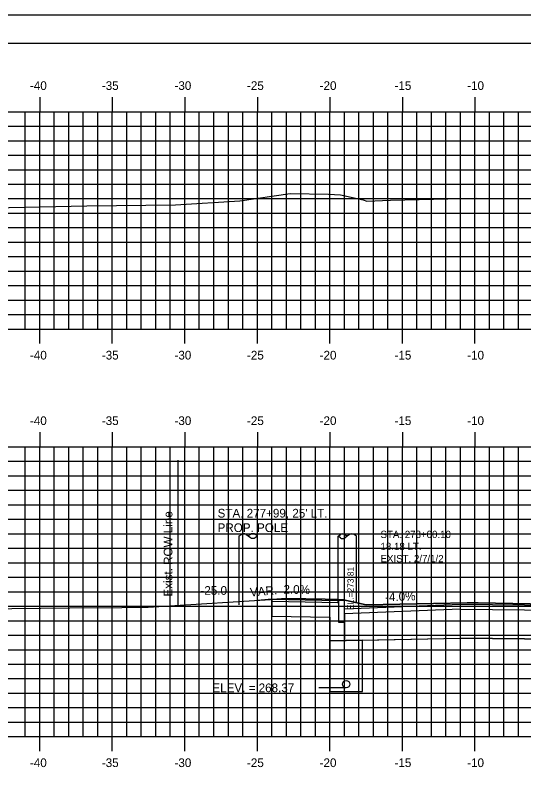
# Model space of a CAD drawing. Extents: x 854453 to 854623, y 366268 to 366378.
# Drawn here: x 854494.8 to 854529.8, y 366325.6 to 366378.2 of the extents above; entities that cross this region are included whole.
import ezdxf

# ---------------------------------------------------------------- set-up
doc = ezdxf.new("R2010")
doc.units = 0
for name, color, linetype in [('ANNOTATION', 7, 'Continuous'), ('BORDER', 7, 'Continuous'), ('D_Curb_Type_1_Lt', 7, 'Continuous'), ('D_Roadway_Edge_Shoulder', 7, 'Continuous'), ('D_Roadway_FinishedGrade', 7, 'Continuous'), ('D_Roadway_Sidewalks_Paved', 7, 'Continuous'), ('D_Roadway_SubGrade', 7, 'Continuous'), ('D_Text_Monospaced', 7, 'Continuous'), ('D_Text_Standard', 7, 'Continuous'), ('D_Utilities_Pole_Joint', 7, 'Continuous'), ('D_Utilities_Text', 7, 'Continuous'), ('E_ROW_Line', 7, 'Continuous'), ('H_V ANNOTATION', 7, 'Continuous'), ('JUNK COM EXC', 7, 'Continuous'), ('junk strct exc', 7, 'Continuous'), ('MAJOR', 7, 'Continuous'), ('MINOR', 7, 'Continuous'), ('PDRAIN', 7, 'Continuous'), ('PLOT BOUNDARY', 7, 'Continuous'), ('S_Roadway_Centerline', 7, 'Continuous'), ('S_Utilities_Pole_Power', 7, 'Continuous')]:
    doc.layers.add(name, color=color, linetype=linetype)

msp = doc.modelspace()

# ---------------------------------------------------------------- linework, layer by layer
at = {"layer": 'BORDER'}
msp.add_line((854621.439, 366376.236), (854461.439, 366376.236), dxfattribs=at)
at = {"layer": 'D_Curb_Type_1_Lt'}
msp.add_lwpolyline([(854517.022, 366337.795), (854517.022, 366336.295), (854517.439, 366336.295), (854517.439, 366337.795)], close=True, dxfattribs=at)
at = {"layer": 'D_Roadway_Edge_Shoulder'}
msp.add_lwpolyline([(854517.439, 366337.212), (854525.439, 366337.532), (854536.439, 366337.422), (854547.439, 366337.202), (854555.437, 366336.882)], dxfattribs=at)
at = {"layer": 'D_Roadway_FinishedGrade'}
msp.add_line((854512.434, 366337.887), (854511.439, 366337.804), dxfattribs=at)
at = {"layer": 'D_Roadway_Sidewalks_Paved'}
msp.add_lwpolyline([(854512.434, 366337.887), (854517.022, 366337.795), (854517.022, 366337.629), (854512.434, 366337.721)], close=True, dxfattribs=at)
at = {"layer": 'D_Roadway_SubGrade'}
msp.add_lwpolyline([(854512.434, 366337.721), (854512.434, 366336.72), (854516.439, 366336.64), (854516.439, 366335.019), (854517.439, 366335.039)], dxfattribs=at)
for points in [[(854525.439, 366337.199), (854517.439, 366336.879), (854517.439, 366335.039), (854525.439, 366335.199)], [(854525.439, 366335.199), (854525.439, 366337.199), (854536.439, 366337.089), (854547.439, 366336.869), (854547.439, 366334.869), (854536.439, 366335.089)]]:
    msp.add_lwpolyline(points, close=True, dxfattribs=at)
at = {"layer": 'D_Text_Standard'}
msp.add_lwpolyline([(854517.564, 366331.768), (854516.366, 366331.768), (854515.686, 366331.768)], dxfattribs=at)
at = {"layer": 'D_Utilities_Pole_Joint'}
for p, q in [((854510.189, 366342.245), (854510.345, 366342.355)), ((854510.657, 366342.355), (854510.813, 366342.245)), ((854510.969, 366342.355), (854510.813, 366342.245)), ((854511.439, 366342.245), (854511.282, 366342.355)), ((854510.189, 366337.487), (854510.189, 366342.245)), ((854510.813, 366342.245), (854510.969, 366342.134)), ((854511.282, 366342.134), (854511.439, 366342.245)), ((854511.439, 366337.487), (854511.439, 366342.245))]:
    msp.add_line(p, q, dxfattribs=at)
for centre, start, end in [((854510.501, 366342.134), 90, 125.2644), ((854510.501, 366342.134), 54.7356, 90), ((854511.126, 366342.134), 90, 125.2644), ((854511.126, 366342.134), 54.7356, 90), ((854511.126, 366342.355), 234.7356, 270), ((854511.126, 366342.355), 270, 305.2644)]:
    msp.add_arc(centre, 0.271, start, end, dxfattribs=at)
at = {"layer": 'E_ROW_Line'}
msp.add_line((854505.984, 366337.468), (854505.984, 366347.468), dxfattribs=at)
at = {"layer": 'JUNK COM EXC'}
for points in [[(854512.435, 366337.865), (854512.434, 366337.865), (854512.434, 366336.72), (854516.439, 366336.64), (854516.439, 366335.019), (854525.439, 366335.199), (854536.439, 366335.089)], [(854537.42, 366337.418), (854526.661, 366337.64), (854525.893, 366337.635), (854518.949, 366337.49), (854517.372, 366337.843), (854516.983, 366337.854), (854516.109, 366337.876), (854513.45, 366337.928), (854512.435, 366337.865)]]:
    msp.add_lwpolyline(points, dxfattribs=at)
at = {"layer": 'junk strct exc'}
msp.add_lwpolyline([(854516.439, 366335.019), (854516.439, 366331.518), (854518.689, 366331.518), (854518.689, 366335.064)], close=True, dxfattribs=at)
at = {"layer": 'MAJOR'}
for p, q in [((854496.439, 366372.523), (854496.439, 366371.521)), ((854501.439, 366372.523), (854501.439, 366371.521)), ((854506.439, 366372.523), (854506.439, 366371.521)), ((854511.439, 366372.523), (854511.439, 366371.521)), ((854516.439, 366372.523), (854516.439, 366371.521)), ((854521.439, 366372.523), (854521.439, 366371.521)), ((854526.439, 366372.523), (854526.439, 366371.521)), ((854466.439, 366371.521), (854606.439, 366371.521)), ((854496.439, 366356.521), (854496.439, 366371.521)), ((854501.439, 366356.521), (854501.439, 366371.521)), ((854506.439, 366356.521), (854506.439, 366371.521)), ((854511.439, 366356.521), (854511.439, 366371.521)), ((854516.439, 366356.521), (854516.439, 366371.521)), ((854521.439, 366356.521), (854521.439, 366371.521)), ((854526.439, 366356.521), (854526.439, 366371.521)), ((854466.439, 366366.521), (854606.439, 366366.521)), ((854466.439, 366361.521), (854606.439, 366361.521)), ((854466.439, 366356.521), (854606.439, 366356.521)), ((854466.439, 366356.521), (854606.439, 366356.521)), ((854496.439, 366355.519), (854496.439, 366356.521)), ((854501.439, 366355.519), (854501.439, 366356.521)), ((854506.439, 366355.519), (854506.439, 366356.521)), ((854511.439, 366355.519), (854511.439, 366356.521)), ((854516.439, 366355.519), (854516.439, 366356.521)), ((854521.439, 366355.519), (854521.439, 366356.521)), ((854526.439, 366355.519), (854526.439, 366356.521)), ((854496.439, 366349.403), (854496.439, 366348.401)), ((854501.439, 366349.403), (854501.439, 366348.401)), ((854506.439, 366349.403), (854506.439, 366348.401)), ((854511.439, 366349.403), (854511.439, 366348.401)), ((854516.439, 366349.403), (854516.439, 366348.401)), ((854521.439, 366349.403), (854521.439, 366348.401)), ((854526.439, 366349.403), (854526.439, 366348.401)), ((854466.439, 366348.401), (854606.439, 366348.401)), ((854466.439, 366348.401), (854606.439, 366348.401)), ((854496.439, 366328.401), (854496.439, 366348.401)), ((854501.439, 366328.401), (854501.439, 366348.401)), ((854506.439, 366328.401), (854506.439, 366348.401)), ((854511.439, 366328.401), (854511.439, 366348.401)), ((854516.439, 366328.401), (854516.439, 366348.401)), ((854521.439, 366328.401), (854521.439, 366348.401)), ((854526.439, 366328.401), (854526.439, 366348.401)), ((854466.439, 366343.401), (854606.439, 366343.401)), ((854466.439, 366338.401), (854606.439, 366338.401)), ((854466.439, 366333.401), (854606.439, 366333.401)), ((854466.439, 366328.401), (854606.439, 366328.401)), ((854466.439, 366328.401), (854606.439, 366328.401)), ((854496.439, 366327.399), (854496.439, 366328.401)), ((854501.439, 366327.399), (854501.439, 366328.401)), ((854506.439, 366327.399), (854506.439, 366328.401)), ((854511.439, 366327.399), (854511.439, 366328.401)), ((854516.439, 366327.399), (854516.439, 366328.401)), ((854521.439, 366327.399), (854521.439, 366328.401)), ((854526.439, 366327.399), (854526.439, 366328.401))]:
    msp.add_line(p, q, dxfattribs=at)
at = {"layer": 'MINOR'}
for p, q in [((854495.439, 366356.521), (854495.439, 366371.521)), ((854497.439, 366356.521), (854497.439, 366371.521)), ((854498.439, 366356.521), (854498.439, 366371.521)), ((854499.439, 366356.521), (854499.439, 366371.521)), ((854500.439, 366356.521), (854500.439, 366371.521)), ((854502.439, 366356.521), (854502.439, 366371.521)), ((854503.439, 366356.521), (854503.439, 366371.521)), ((854504.439, 366356.521), (854504.439, 366371.521)), ((854505.439, 366356.521), (854505.439, 366371.521)), ((854507.439, 366356.521), (854507.439, 366371.521)), ((854508.439, 366356.521), (854508.439, 366371.521)), ((854509.439, 366356.521), (854509.439, 366371.521)), ((854510.439, 366356.521), (854510.439, 366371.521)), ((854512.439, 366356.521), (854512.439, 366371.521)), ((854513.439, 366356.521), (854513.439, 366371.521)), ((854514.439, 366356.521), (854514.439, 366371.521)), ((854515.439, 366356.521), (854515.439, 366371.521)), ((854517.439, 366356.521), (854517.439, 366371.521)), ((854518.439, 366356.521), (854518.439, 366371.521)), ((854519.439, 366356.521), (854519.439, 366371.521)), ((854520.439, 366356.521), (854520.439, 366371.521)), ((854522.439, 366356.521), (854522.439, 366371.521)), ((854523.439, 366356.521), (854523.439, 366371.521)), ((854524.439, 366356.521), (854524.439, 366371.521)), ((854525.439, 366356.521), (854525.439, 366371.521)), ((854527.439, 366356.521), (854527.439, 366371.521)), ((854528.439, 366356.521), (854528.439, 366371.521)), ((854529.439, 366356.521), (854529.439, 366371.521)), ((854466.439, 366370.521), (854606.439, 366370.521)), ((854466.439, 366369.521), (854606.439, 366369.521)), ((854466.439, 366368.521), (854606.439, 366368.521)), ((854466.439, 366367.521), (854606.439, 366367.521)), ((854466.439, 366365.521), (854606.439, 366365.521)), ((854466.439, 366364.521), (854606.439, 366364.521)), ((854466.439, 366363.521), (854606.439, 366363.521)), ((854466.439, 366362.521), (854606.439, 366362.521)), ((854466.439, 366360.521), (854606.439, 366360.521)), ((854466.439, 366359.521), (854606.439, 366359.521)), ((854466.439, 366358.521), (854606.439, 366358.521)), ((854466.439, 366357.521), (854606.439, 366357.521)), ((854495.439, 366328.401), (854495.439, 366348.401)), ((854497.439, 366328.401), (854497.439, 366348.401)), ((854498.439, 366328.401), (854498.439, 366348.401)), ((854499.439, 366328.401), (854499.439, 366348.401)), ((854500.439, 366328.401), (854500.439, 366348.401)), ((854502.439, 366328.401), (854502.439, 366348.401)), ((854503.439, 366328.401), (854503.439, 366348.401)), ((854504.439, 366328.401), (854504.439, 366348.401)), ((854505.439, 366328.401), (854505.439, 366348.401)), ((854507.439, 366328.401), (854507.439, 366348.401)), ((854508.439, 366328.401), (854508.439, 366348.401)), ((854509.439, 366328.401), (854509.439, 366348.401)), ((854510.439, 366328.401), (854510.439, 366348.401)), ((854512.439, 366328.401), (854512.439, 366348.401)), ((854513.439, 366328.401), (854513.439, 366348.401)), ((854514.439, 366328.401), (854514.439, 366348.401)), ((854515.439, 366328.401), (854515.439, 366348.401)), ((854517.439, 366328.401), (854517.439, 366348.401)), ((854518.439, 366328.401), (854518.439, 366348.401)), ((854519.439, 366328.401), (854519.439, 366348.401)), ((854520.439, 366328.401), (854520.439, 366348.401)), ((854522.439, 366328.401), (854522.439, 366348.401)), ((854523.439, 366328.401), (854523.439, 366348.401)), ((854524.439, 366328.401), (854524.439, 366348.401)), ((854525.439, 366328.401), (854525.439, 366348.401)), ((854527.439, 366328.401), (854527.439, 366348.401)), ((854528.439, 366328.401), (854528.439, 366348.401)), ((854529.439, 366328.401), (854529.439, 366348.401)), ((854466.439, 366347.401), (854606.439, 366347.401)), ((854466.439, 366346.401), (854606.439, 366346.401)), ((854466.439, 366345.401), (854606.439, 366345.401)), ((854466.439, 366344.401), (854606.439, 366344.401)), ((854466.439, 366342.401), (854606.439, 366342.401)), ((854466.439, 366341.401), (854606.439, 366341.401)), ((854466.439, 366340.401), (854606.439, 366340.401)), ((854466.439, 366339.401), (854606.439, 366339.401)), ((854466.439, 366337.401), (854606.439, 366337.401)), ((854466.439, 366336.401), (854606.439, 366336.401)), ((854466.439, 366335.401), (854606.439, 366335.401)), ((854466.439, 366334.401), (854606.439, 366334.401)), ((854466.439, 366332.401), (854606.439, 366332.401)), ((854466.439, 366331.401), (854606.439, 366331.401)), ((854466.439, 366330.401), (854606.439, 366330.401)), ((854466.439, 366329.401), (854606.439, 366329.401))]:
    msp.add_line(p, q, dxfattribs=at)
at = {"layer": 'PDRAIN'}
msp.add_lwpolyline([(854516.439, 366335.019), (854516.439, 366331.518), (854518.689, 366331.518), (854518.689, 366335.019)], dxfattribs=at)
msp.add_circle((854517.564, 366332.018), 0.25, dxfattribs=at)
at = {"layer": 'PLOT BOUNDARY'}
msp.add_lwpolyline([(854453.345, 366268.177), (854623.345, 366268.177), (854623.345, 366378.177), (854453.345, 366378.177)], close=True, dxfattribs=at)
at = {"layer": 'S_Roadway_Centerline'}
for points in [[(854481.432, 366364.645), (854499.682, 366365.016), (854505.789, 366365.097), (854510.235, 366365.377), (854513.7, 366365.877), (854516.347, 366365.82), (854517.17, 366365.79), (854518.74, 366365.436), (854518.986, 366365.357), (854520.609, 366365.414), (854526.543, 366365.558), (854529.37, 366365.524), (854537.587, 366365.357), (854540.64, 366365.284), (854549.757, 366364.919), (854555.961, 366364.885), (854557.7, 366364.856), (854557.75, 366364.876), (854558.145, 366365.029), (854560.033, 366365.848), (854560.601, 366365.825), (854560.855, 366365.814), (854564.488, 366366.083), (854568.525, 366366.364)], [(854484.492, 366337.138), (854498.521, 366337.292), (854502.099, 366337.307), (854503.906, 366337.34), (854513.45, 366337.928), (854516.109, 366337.876), (854516.983, 366337.854), (854517.372, 366337.843), (854518.949, 366337.49), (854518.949, 366337.49), (854525.893, 366337.635), (854526.661, 366337.64), (854537.42, 366337.418)]]:
    msp.add_lwpolyline(points, dxfattribs=at)
at = {"layer": 'S_Utilities_Pole_Power'}
for p, q in [((854517.012, 366342.228), (854517.168, 366342.338)), ((854517.481, 366342.338), (854517.637, 366342.228)), ((854517.794, 366342.338), (854517.637, 366342.228)), ((854518.262, 366342.228), (854518.106, 366342.338)), ((854517.012, 366337.609), (854517.015, 366342.228)), ((854517.168, 366342.117), (854517.012, 366342.228)), ((854517.637, 366342.228), (854517.481, 366342.117)), ((854518.262, 366337.609), (854518.265, 366342.228))]:
    msp.add_line(p, q, dxfattribs=at)
for centre, start, end in [((854517.325, 366342.117), 90, 125.2644), ((854517.325, 366342.117), 54.7356, 90), ((854517.95, 366342.117), 90, 125.2644), ((854517.95, 366342.117), 54.7356, 90), ((854517.325, 366342.338), 234.7356, 270), ((854517.325, 366342.338), 270, 305.2644)]:
    msp.add_arc(centre, 0.271, start, end, dxfattribs=at)

# ---------------------------------------------------------------- texts
at = {"layer": 'ANNOTATION'}
for s, rotation, p in [('VAR.', 4.7756, (854510.956, 366338.065)), ('2.0%', 358.8542, (854513.231, 366338.271)), ('-4.0%', 2.2906, (854520.255, 366337.726))]:
    msp.add_text(s, height=0.6, rotation=rotation, dxfattribs=at).set_placement(p)
at = {"layer": 'D_Text_Monospaced'}
for s, height, p in [('STA. 278+00.10', 0.49998, (854519.929, 366342.107)), ('18.18 LT.', 0.5, (854519.929, 366341.273)), ('EXIST. 2/7/1/2', 0.49998, (854519.929, 366340.433))]:
    msp.add_text(s, height=height, dxfattribs=at).set_placement(p)
at = {"layer": 'D_Text_Standard'}
msp.add_text(' EL.=273.81', height=0.4335, rotation=90, dxfattribs=at).set_placement((854518.082, 366336.976))
for s, p in [("-25.0'", (854507.518, 366338.186)), ('ELEV. = 268.37', (854508.339, 366331.468))]:
    msp.add_text(s, height=0.6, dxfattribs=at).set_placement(p)
at = {"layer": 'D_Utilities_Text'}
for s, p in [("STA. 277+99, 25' LT.", (854508.698, 366343.517)), ('PROP. POLE', (854508.698, 366342.517))]:
    msp.add_text(s, height=0.6, dxfattribs=at).set_placement(p)
at = {"layer": 'E_ROW_Line'}
msp.add_text('Exist. ROW Line', height=0.6, rotation=90, dxfattribs=at).set_placement((854505.584, 366338.068))
at = {"layer": 'H_V ANNOTATION'}
for s, p in [('-40', (854495.764, 366373.021)), ('-35', (854500.719, 366373.021)), ('-30', (854505.727, 366373.021)), ('-25', (854510.724, 366373.021)), ('-20', (854515.732, 366373.021)), ('-15', (854520.895, 366373.021)), ('-10', (854525.903, 366373.021)), ('-40', (854495.764, 366354.421)), ('-35', (854500.719, 366354.421)), ('-30', (854505.727, 366354.421)), ('-25', (854510.724, 366354.421)), ('-20', (854515.732, 366354.421)), ('-15', (854520.895, 366354.421)), ('-10', (854525.903, 366354.421)), ('-40', (854495.764, 366349.901)), ('-35', (854500.719, 366349.901)), ('-30', (854505.727, 366349.901)), ('-25', (854510.724, 366349.901)), ('-20', (854515.732, 366349.901)), ('-15', (854520.895, 366349.901)), ('-10', (854525.903, 366349.901)), ('-40', (854495.764, 366326.301)), ('-35', (854500.719, 366326.301)), ('-30', (854505.727, 366326.301)), ('-25', (854510.724, 366326.301)), ('-20', (854515.732, 366326.301)), ('-15', (854520.895, 366326.301)), ('-10', (854525.903, 366326.301))]:
    msp.add_text(s, height=0.6, dxfattribs=at).set_placement(p)

doc.saveas('drawing.dxf')
